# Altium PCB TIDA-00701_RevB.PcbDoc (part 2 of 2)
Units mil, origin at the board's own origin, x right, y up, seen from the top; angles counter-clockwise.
Board outline 4724.41 x 3228.35 mil, 2 copper layers (Top Layer, Bottom Layer), stack 62 mil thick; 170 components, 75 nets, 385 pads, 92 vias.
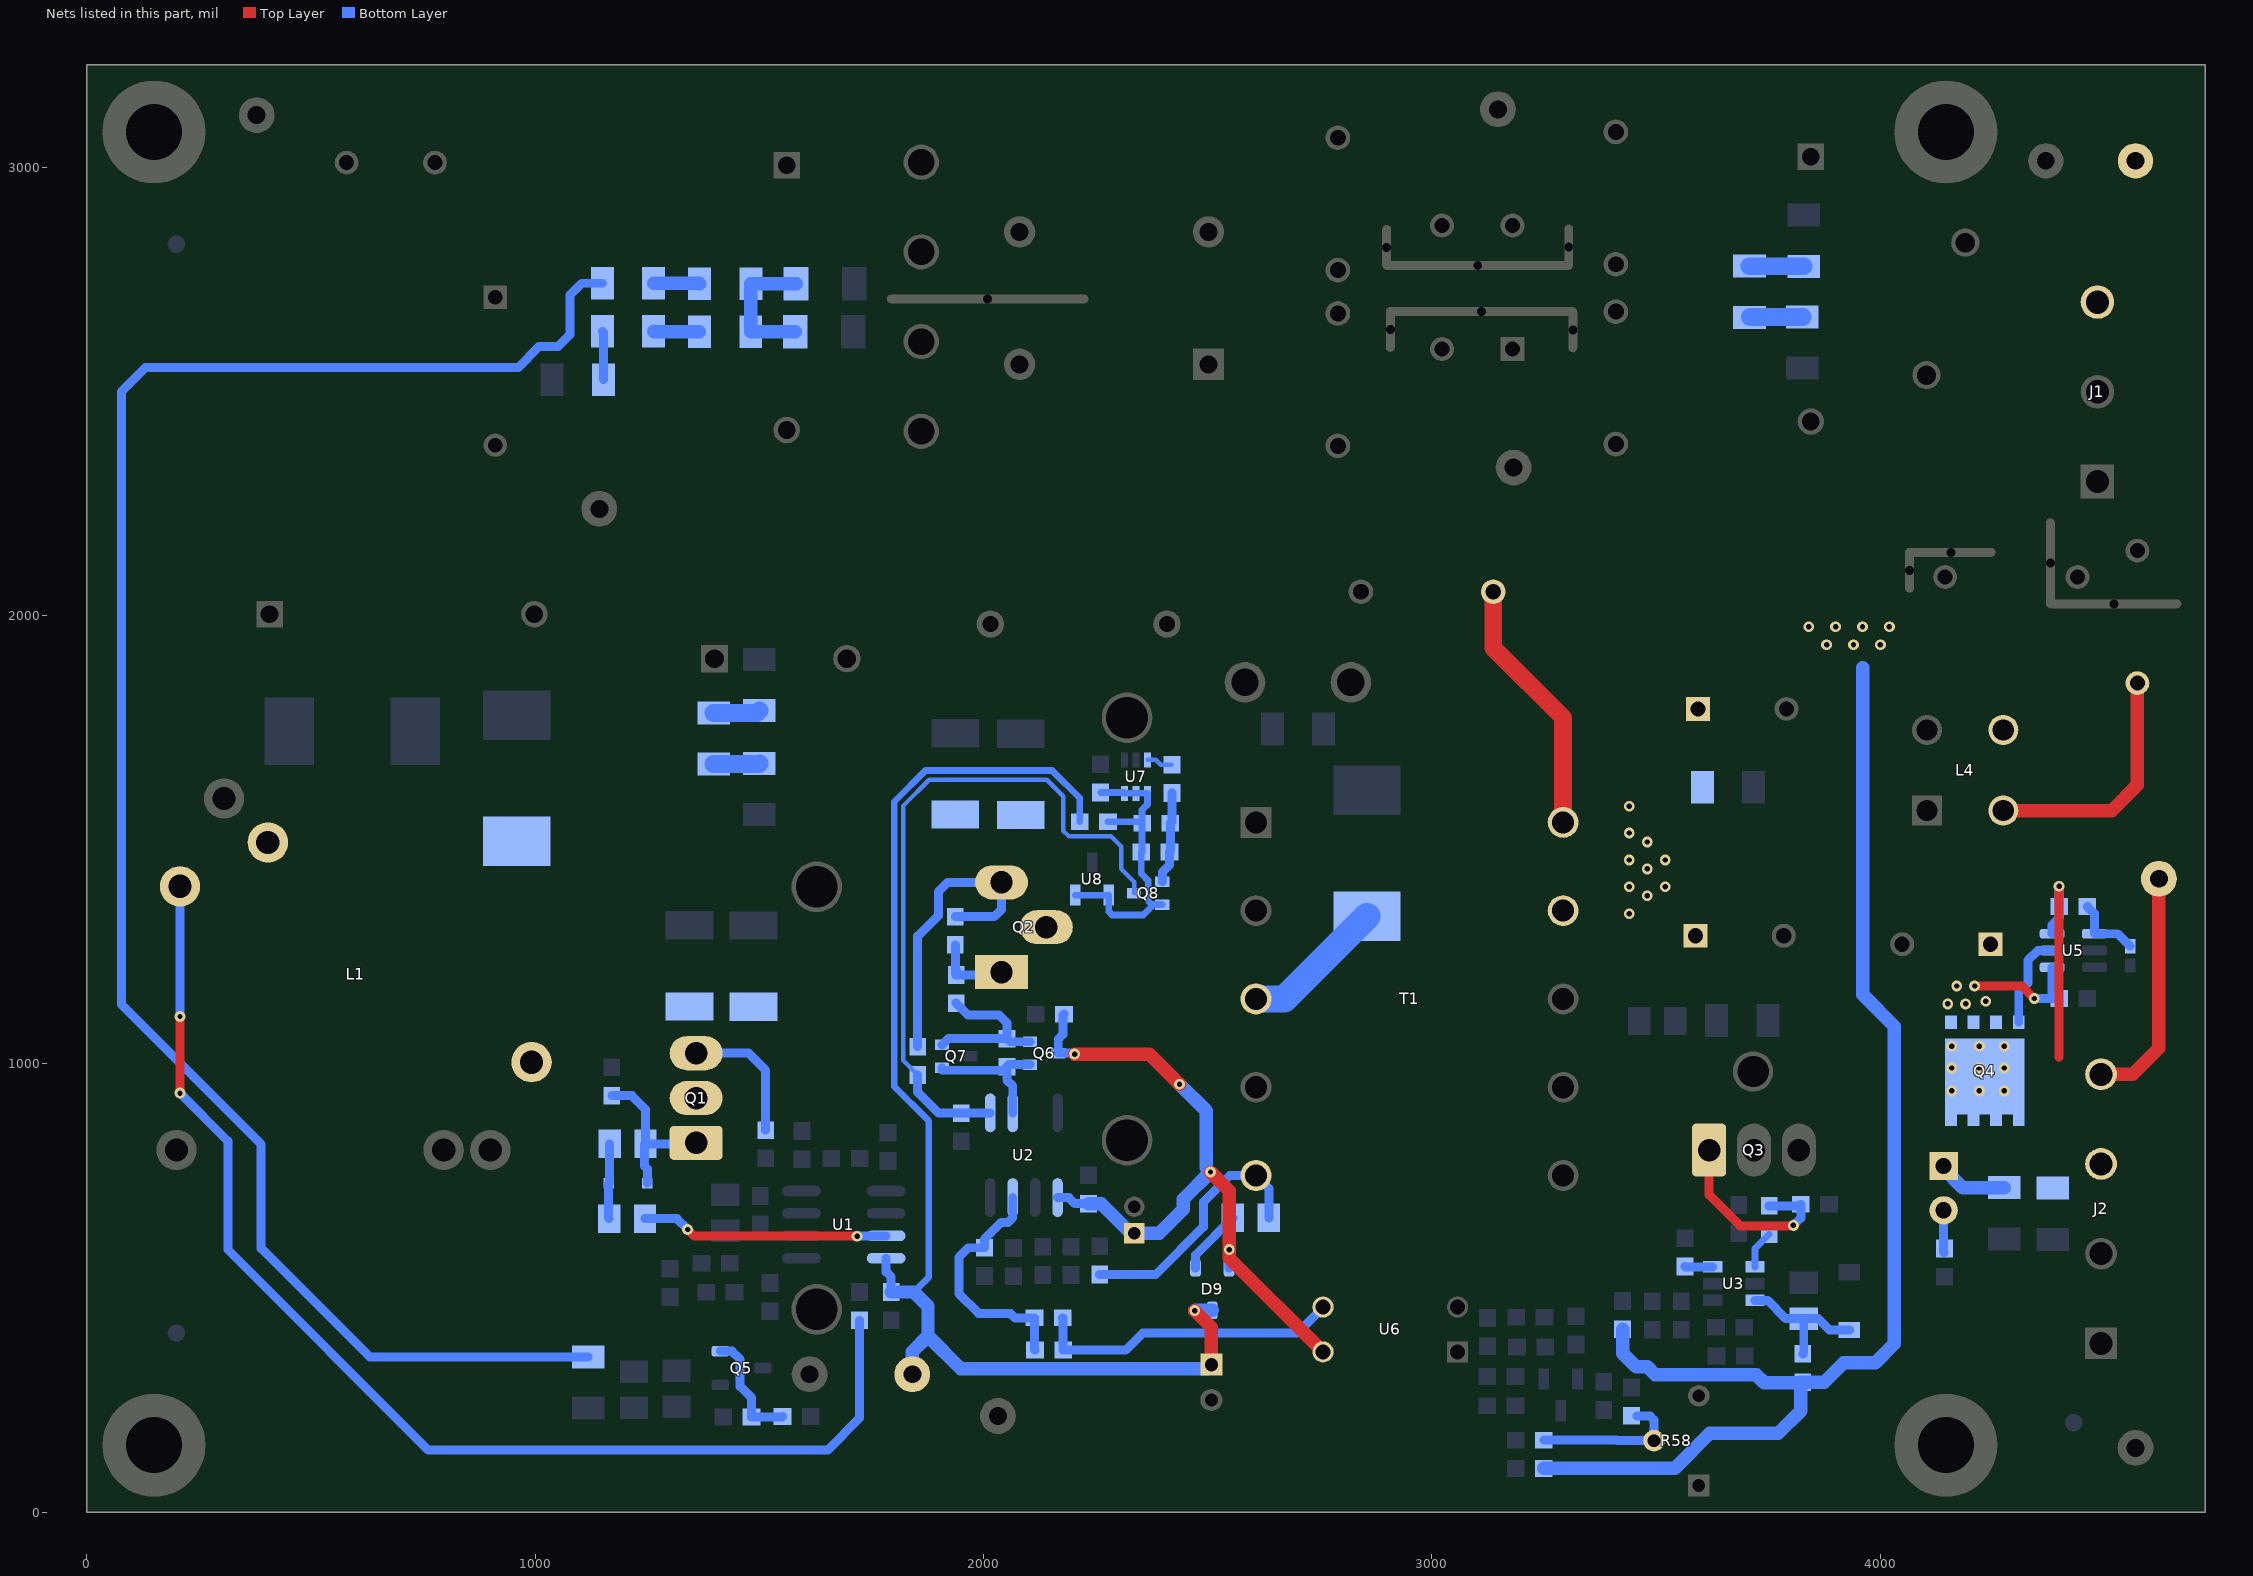
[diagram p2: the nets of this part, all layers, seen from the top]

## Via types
v1: diameter 24, hole 12, Top Layer to Bottom Layer, 92 vias

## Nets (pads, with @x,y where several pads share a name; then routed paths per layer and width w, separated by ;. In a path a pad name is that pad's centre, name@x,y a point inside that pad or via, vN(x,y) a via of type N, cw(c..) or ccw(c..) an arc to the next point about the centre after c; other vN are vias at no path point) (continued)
NetC29_1: C29.1 C30.1 C35.2 L4.4 R37.1 R42.1 R46.1 R53.2 T1.9 T1.10 | length 3528.3
  Top Layer w40: C35.2@3136.64,2053 3136.64,1928 3292.52,1772.12 T1.10@3292.52,1538.7
  Bottom Layer w30: R46.1@3249.5,98 3541.43,98 3619.59,176.16 3772,176.16 3822,226.16 R37.1@3822,290.5 ; R42.1@3425,408.5 3425,355 3455,325 3480.41,325 3498.11,307.3 3722.7,307.3 3740.5,289.5 3821,289.5 R37.1@3822,290.5 ; 3961,1884 3961,1154 4031,1084 4031,376 3989,334 3918,334 3874.5,290.5 R37.1@3827,290.5 R37.1@3822,290.5
  other v1: 3440,1335 3480,1375 3440,1395 3520,1395 3480,1435 3440,1455 3520,1455 3480,1495 3440,1515 3440,1575 3880,1935 3940,1935 4000,1935 3840,1975 3900,1975 3960,1975 4020,1975
NetC31_1: C31.1 C34.1 C39.1 L4.2 Q4.1 Q4.2 Q4.3 U5.4 | length 814.1
  Top Layer w20: v1(4210,1174) 4315,1174 v1(4343,1146)
  Top Layer w30: L4.2@4274.04,1565.04 4516.04,1565.04 4573,1622 C39.1@4573,1849.36
  Bottom Layer w20: v1(4343,1146) 4390,1146 4382.76,1153.24 U5.4@4382.76,1215.6
  other v1: 4150,1134 4190,1134 4235,1140 4170,1174
NetC32_1: C32.1 C33.1 D6.1 J2.3 J2.4 Q4.5 Q4.6 Q4.7 Q4.8 Q4.9 R52.1 TP8.1 U5.6 | length 1183.8
  Top Layer w20: 4398,1015 4398,1396 v1(4398.5,1396.5)
  Top Layer w30: J2.4@4492,977 4563,977 4621,1035 TP8.1@4621,1413
  Bottom Layer w20: U5.6@4382.76,1290.4 4382.76,1310.49 4398.5,1326.24 R52.1@4398.5,1351 v1(4398.5,1396.5)
  Bottom Layer w30: D6.1@4141,772.21 4141,766.21 4183.13,724.09 C32.1@4276,724.09
  other v1: 4158.98,940 4220.8,940 4276.11,940 4158.98,990.97 4220.8,990.97 4276.11,990.97 4158.98,1039.59 4220.8,1039.59 4276.11,1039.59
NetC36_1: C36.1 Q8.3 R29.1 U2.5 | length 1565.6
  Bottom Layer w10: R29.1@1853,975.5 1821.3,1007.2 1821.3,1576.3 1879,1634 2141,1634 2178,1597 2178,1519.73 2189.43,1508.3 2283.7,1508.3 2307,1485 2307,1435 2335.5,1406.5 Q8.3@2335.5,1381
  Bottom Layer w20: R29.1@1853,975.5 1853,937 1899.5,890.5 C36.1@1950,890.5 U2.5@2014.57,890.5
NetC37_2: C37.2 D11.1 R37.2 U3.6 | length 310.5
  Bottom Layer w20: U3.6@3720.24,472.6 3748.4,472.6 3789,432 C37.2@3822,432 ; R37.2@3827,353.5 3829,355.5 C37.2@3829,432 3861,432 3886,407 3930.53,407 D11.1@3931,406.53
NetC38_1: C38.1 R13.2 R34.2 U2.3 | length 556.9
  Bottom Layer w20: U2.3@2065.07,702.02 2065.07,657.07 2054.71,646.71 2039.56,646.71 2002,609.15 R34.2@2002,590.15 1966.15,590.15 1945,569 1945,488 1989,444 2060,444 2069.97,434.03 C38.1@2113.5,434.03 2113.5,363.03 R13.2@2114.5,362.03
NetC38_2: C38.2 R13.1 U6.3 | length 691.7
  Bottom Layer w20: C38.2@2176.5,434.03 2177.5,433.03 R13.1@2177.5,362.03 2317.03,362.03 2355,400 2699,400 U6.3@2757,458
NetC42_1: C42.1 Q8.1 R25.2 R33.1 | length 206.5
  Bottom Layer w20: Q8.1@2398.5,1406.59 2398.5,1427.5 2414.5,1443.5 R33.1@2414.5,1473 2416.5,1475 C42.1@2416.5,1537 2420,1540.5 R25.2@2420,1604.15
NetC42_2: C42.2 C43.1 Q8.2 R33.2 R35.2 U7.4 U7.5 U7.6 U8.1 U8.2 | length 693.8
  Bottom Layer w15: U8.2@2204.6,1376.57 U8.1@2279.4,1376.57 2279.4,1339.6 2286.56,1332.44 2356.06,1332.44 2377.31,1353.69 ; C43.1@2261,1605.5 2312.5,1605.5 U7.6@2314.41,1603.6 U7.5@2340,1603.6 U7.4@2365.59,1603.6 2365.59,1578.86 2353.5,1566.77 C42.2@2353.5,1537 ; R35.2@2277.5,1540 2350.5,1540 C42.2@2353.5,1537 ; R33.2@2351.5,1473 2351.5,1424.5 2367,1409 2367,1364 2377.31,1353.69 ; R33.2@2353.5,1470.83 C42.2@2353.5,1537 ; Q8.2@2398.5,1355.41 2379.03,1355.41 2377.31,1353.69
NetD1_2: D1.2 L1.2 L1.4 Q1.2
NetD3_1: D3.1 R14.1 R15.2 | length 168.5
  Bottom Layer w20: R15.2@1165,655 1163.69,656.31 D3.1@1163.69,734 1166,736.31 R14.1@1166,822
NetD3_2: D3.2 Q1.1 R14.2 R16.1 | length 369.9
  Bottom Layer w20: R16.1@1171,929.5 1215.5,929.5 1246,899 R14.2@1246,822 ; D3.2@1250.31,734 1250.31,765.69 1244,772 1244,820 R14.2@1246,822 ; Q1.1@1359,824 1357,822 R14.2@1246,822
NetD4_1: D4.1 D5.1 R3.1 R17.2 | length 306.5
  Bottom Layer w30: R3.1@1480.79,2633.06 R3.1@1480.79,2633.06 R17.2@1480.85,2740.1 ; R17.2@1480.89,2740.06 D4.1@1581.75,2740.06 ; R3.1@1481.2,2632.65 D5.1@1579.75,2632.65
NetD6_2: D6.2 R55.2 | length 94.2
  Bottom Layer w20: D6.2@4141,673.79 4141,581 R55.2@4142,580
NetD8_2: D8.2 Q2.2 T1.3 | length 323.9
  Bottom Layer w60: T1.3@2607.48,1145 2670.49,1145 D8.2@2855,1329.51
NetD9_1: D9.1 R30.1 | length 146.3
  Bottom Layer w20: D9.1@2472.6,545.24 2472.6,573.6 R30.1@2556,657
NetD12_1: D12.1 R52.2 U5.1 | length 158.4
  Bottom Layer w20: R52.2@4461.5,1351 4477.24,1335.25 U5.1@4477.24,1290.4 4529.25,1290.4 D12.1@4557,1262.65
NetF1_2: F1.2 J1.3 XF1.2
NetL1_8: L1.8 R12.2 | length 2695.4
  Top Layer w20: v1(208,935) v1(208,1106)
  Bottom Layer w20: v1(208,935) 315,828 315,586 762,139 1652,139 1723,210 R12.2@1723,428.5 ; v1(208,1106) L1.8@208,1396
NetQ1_3: Q1.3 R1.2 R2.2 R11.2 | length 304.2
  Bottom Layer w20: Q1.3@1359,1024 1476,1024 1514,986 R11.2@1514,852.5
NetQ2_1: Q2.1 R28.2 R47.2 | length 171.7
  Bottom Layer w20: R28.2@1937,1202.5 R47.2@1937,1265.5 ; R28.2@1938,1201.5 R28.2@1941.5,1205 ; R28.2@1939,1198.5 2033.5,1198.5 Q2.1@2040,1205
NetQ2_3: Q2.3 R26.2 R27.2 R29.2 R47.1 | length 684.1
  Bottom Layer w20: R29.2@1853,1038.5 1853,1285 1899,1331 1899,1384 1920,1405 Q2.3@2040,1405 2040,1345 2023.5,1328.5 R47.1@1937,1328.5
NetQ3_1: Q3.1 R43.1 R44.2 | length 442.4
  Top Layer w20: Q3.1@3618,808 3618,708 3687,639 v1@3806,639
  Bottom Layer w20: R44.2@3752,683.5 3819,683.5 R43.1@3822.5,687 3822.5,656.5 v1(3806,640)
NetQ4_4: Q4.4 U5.5 | length 209.1
  Bottom Layer w20: Q4.4@4308.49,1093.3 4308.49,1159.49 4329,1180 4329,1231 4351,1253 U5.5@4382.76,1253
NetQ5_2: Q5.2 R21.1 R60.2 | length 259.9
  Bottom Layer w20: Q5.2@1412.76,359.4 1438.6,359.4 1457,341 1457,281 1482.5,255.5 R21.1@1482.5,213 1550.5,213 R60.2@1551.5,214
NetQ6_1: Q6.1 Q7.1 R36.1 U2.6 | length 314.5
  Bottom Layer w20: Q7.1@1907.5,991.41 1907.5,986 2044.5,986 R36.1@2052,993.5 ; U2.6@2065.07,891 2065.07,950.93 2052,964 R36.1@2052,993.5 ; Q6.1@2103.5,998.41 2056.91,998.41 R36.1@2052,993.5
NetQ6_2: Q6.2 Q7.2 R28.1 R36.2 | length 370.9
  Bottom Layer w20: Q7.2@1907.5,1042.59 1921.41,1056.5 R36.2@2052,1056.5 ; R28.1@1939,1135.5 1965.22,1109.29 2034.29,1109.29 2052,1091.57 R36.2@2052,1056.5 ; Q6.2@2103.5,1049.59 2058.91,1049.59 R36.2@2052,1056.5
NetR3_2: R3.2 R4.1 | length 101.9
  Bottom Layer w30: R4.1@1264.09,2634 1265.03,2633.06 R3.2@1365.62,2633.06
NetR4_2: R4.2 R59.1 | length 108.9
  Bottom Layer w20: R4.2@1149.91,2634 1152.09,2631.83 R59.1@1152.09,2526
NetR6_2: R6.2 R7.2 | length 104
  Bottom Layer w40: R7.2@1398,1783.09 1495.17,1783.09 R6.2@1500,1787.91
NetR7_1: R7.1 R8.2 | length 102.5
  Bottom Layer w40: R7.1@1398,1668.91 1498.83,1668.91 R8.2@1500,1670.09
NetR15_1: R15.1 U1.7 | length 554.2
  Top Layer w20: v1(1340,631) 1355,616 v1(1718,616)
  Bottom Layer w20: R15.1@1245,655 1316,655 v1(1340,631) ; v1(1718,616) 1719,616 1719.72,616.72 U1.7@1782.71,616.72
NetR17_1: R17.1 R18.1 | length 101.9
  Bottom Layer w30: R18.1@1264.14,2741.04 R17.1@1364.73,2741.04 ; R17.1@1365.73,2741.04 R17.1@1366.67,2740.1
NetR18_2: R18.2 R19.2 | length 4093.6
  Bottom Layer w20: R19.2@1118.22,346.81 631.19,346.81 389,589 389,821 77,1133 77,2499 131,2553 961.92,2553 1008.46,2599.54 1050.54,2599.54 1077.92,2626.92 1077.92,2714.92 1104.04,2741.04 R18.2@1149.97,2741.04
NetR22_2: R22.2 R23.1 | length 121.1
  Bottom Layer w30: R23.1@3708,2779.09 R23.1@3708.17,2778.91
  Bottom Layer w40: R23.1@3708.17,2778.91 R22.2@3829,2778.91
NetR23_2: R23.2 R24.1 | length 118.5
  Bottom Layer w30: R23.2@3708,2664.91 R23.2@3709.17,2666.09
  Bottom Layer w40: R23.2@3709.17,2666.09 R24.1@3826,2666.09
NetR25_1: R25.1 U7.3 | length 59.1
  Bottom Layer w10: U7.3@2365.59,1678.4 2383.98,1678.4 2395.24,1667.14 R25.1@2420,1667.14
NetR30_2: R30.2 R31.2 T1.5 | length 578.5
  Bottom Layer w20: R31.2@2259,530.5 2383.91,530.5 2490,636.6 2490,692 2549.3,751.3 T1.5@2607.48,751.3 2636,722.78 R30.2@2636,657
NetR40_1: R40.1 U3.3 | length 62.2
  Bottom Layer w20: R40.1@3564,548.5 3565.1,547.4 U3.3@3625.76,547.4
NetR44_1: R44.1 U3.4 | length 86.3
  Bottom Layer w15: U3.4@3720.24,547.4 3720.24,588.75 R44.1@3752,620.5
NetR56_1: R56.1 R57.2 R58.2 | length 333.5
  Bottom Layer w20: R56.1@3249.5,161 3411,161 3412,160 R58.2@3495.06,160 3495.06,205.94 3486.5,214.5 R57.2@3457,214.5
VCC: C9.1 C19.1 D9.3 R35.1 TP3.1 U1.8 | length 2842.9
  Top Layer w30: v1(2471,450) 2508,413 C19.1@2508,329.37
  Bottom Layer w15: 1844.5,491.5 1878,524.99 1878,872.4 1800.8,949.6 1800.8,1584.79 1870.51,1654.5 2153.03,1654.5 2214.5,1593.02 R35.1@2214.5,1540
  Bottom Layer w20: U1.8@1782.71,566.72 1782.71,536.29 1794,525 C9.1@1794,491.5
  Bottom Layer w30: C9.1@1794,491.5 1844.5,491.5 1876,460 1876,393.33 ; TP3.1@1841,308 1841,358.33 1876,393.33 ; v1(2471,450) 2471.76,450.76 D9.3@2510,450.76 ; C19.1@2508,329.37 2498.96,320.33 1949,320.33 1876,393.33
VDD: C20.1 C21.1 C41.1 D9.2 Q6.3 U2.1 U6.4 | length 1592.6
  Top Layer w30: v1(2203,1022) 2370,1022 v1(2437,955) ; v1(2506,759) 2548,717 v1(2548,586) 2548,567 U6.4@2757,358
  Bottom Layer w20: U2.1@2165.07,702.02 2189.98,702.02 2203.5,688.5 C21.1@2234,688.5 ; C41.1@2179.5,1111 2177,1108.5 2177,1066 2166.5,1055.5 Q6.3@2166.5,1024 2201,1024 v1(2203,1022) ; C20.1@2328.53,622.47 C20.1@2336,622.47 ; D9.2@2547.4,545.24 2547.4,583.4 2548,584 v1(2548,586)
  Bottom Layer w30: C21.1@2234,688.5 2262.5,688.5 C20.1@2328.53,622.47 ; C20.1@2336,622.47 2391.47,622.47 2445,676 2445,698 v1(2506,759) ; v1(2437,955) 2497,895 2497,768
pads on no net: FID1.1 FID2.1 FID3.1 H1.1 H2.1 H3.1 H4.1 R58.1 T1.2 T1.8

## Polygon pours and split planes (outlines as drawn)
NetC29_1 on Bottom Layer "Top Layer-No Net" (solid, remove dead copper, pour order 52): 3246,1710 3246,1519 3246,1246 3264,1228 3287,1228 3618,1228 3632,1242 3632,1310 3632,1825 3668,1861 3692,1861 4182,1861 4237,1806 4238,1805 4238,1753 4238,1721 4250,1709 4286,1709 4337,1709 4346,1718 4347,1719 4347,1754 4347,1959 4301,2005 3462,2005 3429,1972 3429,1925 3429,1742 3412,1725 3261,1725
NetC31_1 on Bottom Layer "Top Layer-No Net" (solid, remove dead copper, pour order 48): 4236,1589 4218,1571 4186,1539 4186,1302.2 4173,1289.2 4173,1261 4178,1256 4201,1233 4231,1233 4285,1233 4316,1264 4316,1362 4370,1416 4370,1564 4370,1580 4355,1595 4350,1600 4268,1600 4247,1600
NetC3_1 on Bottom Layer "M9 Title Sheet-No Net" (solid, pour order 79): 4342,3056 4331,3045 4331,3027 4331,2985 4322,2976 4209,2863 4191,2863 4176,2863 4164,2875 4124,2915 4091,2915 4017,2915 3871,3061 3815,3061 3771,3061 3767,3065 3712,3120 3413,3120 3315,3120 3157,2962 3152,2957 3152,2888 3152,2852 3161,2843 3163,2841 3199,2841 3226,2841 3230,2845 3241,2856 3241,2884 3241,2893 3291,2943 3338,2990 3668,2990 3794,2864 3885,2864 3966,2783 4140,2783 4156,2799 4158,2801 4169,2801 4221,2801 4232,2790 4237,2785 4301,2785 4411,2895 4411,3043 4398,3056
NetC18_2 on Bottom Layer "M9 Title Sheet-No Net" (solid, remove dead copper, pour order 78): 2731,1886 2731,1642 2731,1560 2743,1548 2748,1543 2803,1543 2928,1543 2933,1548 2934,1549 2934,1586 2934,1870 2908,1896 2905,1899 2844,1899 2744,1899
NetC8_1 on Bottom Layer "M9 Title Sheet-No Net" (solid, remove dead copper, pour order 77): 2454,2590 2454,2523 2472,2505 2652,2325 2788,2325 2906,2325 2952,2371 3050,2469 3050,2518 3050,2612 3041,2621 3040,2622 3020,2622 3006,2622 2997,2613 2992,2608 2992,2592 2992,2588 2986,2582 2854,2450 2820,2450 2701,2450 2663,2488 2553,2598 2533,2598 2463,2598 2462,2597 2454,2589
NetC7_1 on Bottom Layer "M9 Title Sheet-No Net" (solid, remove dead copper, pour order 76): 2454,2825.91 2465.92,2814 2568,2814 2586,2832 2586,2879 2701,2994 2855,2994 3008,2841 3042,2841 3051,2850 3051,2894 3051,2973 2905,3119 2775,3119 2653,3119 2554,3020 2454,2920
NetD1_2 on Bottom Layer "M9 Title Sheet-No Net" (solid, remove dead copper, pour order 75): 372,1543 817,1543 834.25,1560.25 1027.76,1560.25 1040.03,1547.97 1040,1438.75 1040,1010 1040,973 1032,965 1017,950 963,950 947,966 947,1010 947,1413 921,1439 372,1439 362,1449 359,1452 359,1484 359,1530
NetC32_1 on Bottom Layer "M9 Title Sheet-No Net" (solid, remove dead copper, pour order 74): 4144,1058 4319,1058 4328,1058 4340,1046 4349,1037 4398,1037 4518,1037 4532,1023 4539,1016 4539,901 4539,712 4526,699 4262,699 4237,699 4220,716 4220,756 4220,817 4205,832 4202,835 4152,835 4146,835 4137,844 4134.57,846.43 4134.57,892 4134.57,1053.57 4139,1058
NetC2_1 on Bottom Layer "M9 Title Sheet-No Net" (solid, remove dead copper, pour order 71): 2379,1961 2518,1822 2518,1808 2518,1522 2531,1509 2538,1502 2569,1502 2643,1502 2672,1531 2672,1739 2672,2107 2661,2118 2659,2120 2464,2120 2395,2120 2382,2107 2379,2104 2379,2032 2379,1961
GND on Bottom Layer "M9 Title Sheet-No Net" (solid, remove dead copper, pour order 70): 883,2397 889,2403 893,2407 924,2407 1221,2407 1359,2269 1370,2258 1435,2258 1920,2258 2053,2125 2082,2096 2082,1896 2082,1893.89 2113,1862.89 2113.89,1862 2227,1862 2306,1862 2376,1792 2384,1784 2384,1752 2384,1742 2357.13,1715.13 2353,1711 2353,1664 2353,1662.28 2337.72,1647 2228,1647 2207,1668 2179,1696 2163,1696 1805,1696 1796,1705 1796,1780 1789,1787 1778,1787 1772,1781 1772,1757 1772,1400 1704,1332 1633,1261 1415,1261 1269,1261 1247,1283 1247,1465 1271,1489 1272,1488 1431,1488 1632,1488 1664,1520 1664,1979 1664,2058 1625,2097 1315,2097 1123,2097 1088,2062 1088,2002 1088,1988 1071,1971 900,1971 883,1988 883,2050 883,2344
NetBR1_1 on Bottom Layer "M9 Title Sheet-No Net" (solid, remove dead copper, pour order 66): 1838,2971 1897,2971 1899,2971 1911,2983 1914,2986 1914,3056 1914,3071 1903,3082 1895,3090 1834,3090 1692,3090 1660,3090 1639,3090 1590,3041 1584,3035 1570,3035 1525,3035 1492,3068 1476,3084 1441,3084 770,3084 757,3071 751,3065 751,3024 751,2982 751,2961 751,2960 761,2950 769,2942 913,2942 1479,2942 1496,2959 1511,2974 1536,2974 1594,2974 1631,2937 1644,2924 1701,2924 1756,2924 1793,2961 1803,2971
NetBR1_2 on Bottom Layer "Bottom Layer-No Net" (solid, remove dead copper, pour order 54): 2105,2771 2123,2789 2123,2790 2123,2813 2123,2889 2123,2908 2117,2914 2116,2915 2072,2915 1989,2915 1926,2852 1925,2851 1904,2851 1829,2851 1821,2843 1821,2789 1821,2778 1827,2772 1828,2771 1852,2771 2105,2771
NetBR1_3 on Bottom Layer "Bottom Layer-No Net" (solid, remove dead copper, pour order 55): 2110.63,2652.64 2128.63,2634.64 2128.63,2633.64 2128.63,2610.64 2128.63,2534.64 2128.63,2515.64 2122.63,2509.64 2121.63,2508.64 2077.63,2508.64 1994.63,2508.64 1931.63,2571.64 1930.63,2572.64 1909.63,2572.64 1834.63,2572.64 1826.63,2580.64 1826.63,2634.64 1826.63,2645.64 1832.63,2651.64 1833.63,2652.64 1857.63,2652.64 2110.63,2652.64
GNDE on Bottom Layer "Bottom Layer-No Net" (solid, remove dead copper, pour order 46): 4441,2334 4441,2173 4420,2152 4410,2142 4410,2088 4410,2071 4415,2066 4423,2058 4451,2058 4481,2058 4482,2058 4489,2065 4493,2069 4493,2098 4493,2106 4501,2114 4502,2115 4552,2115 4602,2115 4605,2118 4606,2119 4606,2148 4606,2314 4606,2326 4595,2337 4593,2339 4506,2339 4445,2339 4441,2335
NetF1_2 on Bottom Layer "Bottom Layer-No Net" (solid, remove dead copper, pour order 41): 4531,3059 4528,3056 4528,2974 4528,2790 4513,2775 4497,2759 4476,2759 4448,2759 4445,2756 4438,2749 4438,2727 4438,2674 4443,2669 4452,2660 4485,2660 4641,2660 4654,2673 4659,2678 4659,2799 4659,3057 4651,3065 4537,3065
GND on Bottom Layer "Top Layer-NetL_1" (solid, remove dead copper, pour order 47): 1922,379 1923,378 1923,124 1923,81 1948,56 1951,53 2068,53 2617,53 2663,99 2668,104 2668,133 2668,966 2631,1003 2433,1003 2191.08,761.08 2151,761.08 2115.92,761.08 2044,833 2043,834 2043,989 2043,1042 2019,1066 2017,1068 1864,1068 1836,1068 1806,1038 1804,1036 1804,932 1852,884 1921,815 1921,754
GND on Bottom Layer "Top Layer-NetL_1" (solid, remove dead copper, pour order 43): 1507,918 1763,918 1800,881 1885,796 1885,705 1885,91 1865,71 1857,63 1645,63 403,63 383,83 327.65,138.35 327.65,556.1 327.65,566.28 359.63,598.27 412.37,651 949,651 1320,651 1356,687 1411,742 1464,742 1471,742 1504,775 1508,779 1508,900 1508,910 1516,918
GND-3 on Bottom Layer "Top Layer-NetL_1" (solid, remove dead copper, pour order 44): 4469,1265 4512,1265 4512,1264 4520,1256 4520,1248 4526,1242 4532,1236 4549,1236 4585,1236 4589,1232 4589,1221 4589,1180 4586,1177 4531,1177 4521,1167 4521,1119 4514,1112 4447,1112 4442,1112 4438,1116 4438,1126 4438,1254 4449,1265
NetQ1_3 on Bottom Layer "Bottom Layer-No Net 6" (solid, remove dead copper, pour order 56): 1274,1164 1274,1003 1292,985 1415,985 1430,1000 1430,1054 1449,1073 1541.56,1073 1559,1090.44 1559,1162.97 1551.96,1170.01 1280.01,1170.01
NetQ2_3 on Bottom Layer "Bottom Layer-No Net 3" (solid, remove dead copper, pour order 49): 1878,1587 1889,1598 2137.96,1598 2147.96,1588 2147.96,1420.96 2095,1368 1886,1368 1878,1376
NetC31_1 on Bottom Layer "Bottom Layer-No Net 8" (solid, remove dead copper, pour order 58): 4186,1302.2 4283.8,1302.2 4296,1290 4296,1193 4279,1176 4279,1075.2 4276,1072.2 4135,1072.2 4129,1078.2 4129,1190.2 4173,1234.2 4173,1289.2
GND-3 on Bottom Layer "Bottom Layer-No Net 11" (solid, remove dead copper, pour order 57): 4645,641 4654,632 4654,286.67 4644.33,277 4641.33,280 4281,280 4228.36,332.64 4228.36,630.36 4239,641
NetC28_2 on Bottom Layer "Top Layer-No Net 11" (solid, remove dead copper, pour order 62): 3254,978 3255,977 3255,721 3271,705 3524,705 3541,722 3541,853 3576,888 3652,888 3677,863 3677,747 3694,730 3745,730 3759,744 3759,916 3746,929 3683,929 3613,999 3275,999
GND-2 on Bottom Layer "Bottom Layer-No Net 4" (solid, remove dead copper, pour order 63): 3692,1792 3692,1012.25 3779,925.25 3779,570 3766,557 3766,532 3760,526 3699,526 3692,519 3692,497 3697,492 3760,492 3775,477 3966,477 3986,497 3986,1057 3885,1158 3885,1796 3863,1818 3862,1817 3717,1817
GND-3 on Top Layer "Top Layer-No Net" (solid, remove dead copper, pour order 45): 4070,1598 4138,1598 4144,1592 4145,1591 4145,1555 4145,1528 4137,1520 4135,1518 4127.4,1518 4114,1504.6 4113,1503.6 4113,1276 4087,1250 4087,1122 4087,619 4096,610 4122,610 4637,610 4649,598 4655,592 4655,583.42 4655,287.67 4645.33,278 4644.33,277 4634,277 4117,277 4106.33,287.67 3932,462 3932,499 3932,1505 3977,1550 4025,1598 4069,1598
GND-2 on Top Layer "Top Layer-No Net" (solid, pour order 42): 3151,524 3151.2,523.8 3151.2,436 3151.2,65.8 3172,45 3224,45 3873,45 3888,60 3888,171.5 3888,1577 3904,1593 3985,1674 4076.05,1674 4103,1674 4123,1674 4127,1674 4132,1674 4137,1679 4143,1685 4143,1693 4143,1807 4137,1813 4132,1818 4048,1818 3718,1818 3692,1792 3692,1685 3692,1012 3781,923 3781,831 3781,709 3753,681 3567,681 3545,659 3502,616 3502,598 3502,556 3479,533 3160,533
NetC3_2 on Top Layer "M9 Title Sheet-No Net" (solid, pour order 80): 3151,2621 3146,2616 3146,2515 3146,2502 3232,2416 3310,2338 3322,2326 3488,2326 3739,2326 3787,2374 3814,2401 3853,2401 3877,2401 3894,2384 3977,2384 4096,2503 4142,2503 4187,2458 4297,2458 4515,2458 4526,2469 4526,2523 4512,2537 4416.85,2537 4371.85,2582 4361,2582 4153,2582 4139,2568 4024,2568 3932,2476 3721,2476 3372,2476 3215,2633 3185,2633 3163,2633
NetC32_1 on Top Layer "M9 Title Sheet-No Net" (solid, remove dead copper, pour order 73): 4144,1058 4319,1058 4328,1058 4340,1046 4349,1037 4398,1037 4518,1037 4532,1023 4539,1016 4539,901 4539,712 4526,699 4262,699 4237,699 4220,716 4220,756 4220,817 4205,832 4202,835 4152,835 4146,835 4137,844 4134.57,846.43 4134.57,892 4134.57,1053.57 4139,1058
NetC2_1 on Top Layer "M9 Title Sheet-No Net" (solid, remove dead copper, pour order 72): 2379,2104 2379,1978 2379,1962 2428,1913 2542,1799 2612,1799 2650,1799 2664,1813 2672,1821 2672,1841 2672,2107 2659,2120 2395,2120 2393,2118
NetBR1_4 on Top Layer "M9 Title Sheet-No Net" (solid, remove dead copper, pour order 69): 904,2772 1181,2772 1212,2741 1511,2442 1518,2442 1582,2442 1609,2469 1621,2481 1759,2481 1771,2481 1799,2453 1891,2453 1905,2439 1906,2438 1906,2394 1906,2384 1892,2370 1891,2369 1818,2369 1606,2369 1594,2381 1593,2382 1572,2382 1531,2382 1512,2363 1376,2363 1318,2421 1105,2634 1030,2634 895,2634 880,2649 880,2753 880,2755.3 894.7,2770 897,2772
NetD1_2 on Top Layer "M9 Title Sheet-No Net" (solid, remove dead copper, pour order 68): 947,1033 947,973 962,958 965,955 1031,955 1156,955 1204,907 1227,884 1254,884 1405,884 1421,900 1421,943 1403,961 1402,962 1314,962 1249,962 1162,1049 963,1049
NetC1_1 on Top Layer "M9 Title Sheet-No Net" (solid, remove dead copper, pour order 67): 254,1898 254,1608 254,1572 274,1552 278,1548 332,1548 365,1581 365,1667 390,1692 454,1692 467,1705 467,1946 438,1975 438,2035 438,2036 485,2083 489,2087 489,2116 489,2903 526,2940 527,2939 593,2939 608,2954 608,3029 594,3043 532,3043 359,3043 350,3034 347,3031 347,2955 347,2065 377,2035 378,2034 378,2004 378,1977 344,1943 299,1943 254,1898
NetBR1_3 on Top Layer "Bottom Layer-No Net" (solid, remove dead copper, pour order 51): 2110.63,2652.64 2128.63,2634.64 2128.63,2633.64 2128.63,2610.64 2128.63,2534.64 2128.63,2515.64 2122.63,2509.64 2121.63,2508.64 2077.63,2508.64 1994.63,2508.64 1931.63,2571.64 1930.63,2572.64 1909.63,2572.64 1834.63,2572.64 1826.63,2580.64 1826.63,2634.64 1826.63,2645.64 1832.63,2651.64 1833.63,2652.64 1857.63,2652.64 2110.63,2652.64
NetBR1_2 on Top Layer "Bottom Layer-No Net" (solid, remove dead copper, pour order 53): 2105,2771 2123,2789 2123,2790 2123,2813 2123,2889 2123,2908 2117,2914 2116,2915 2072,2915 1989,2915 1926,2852 1925,2851 1904,2851 1829,2851 1821,2843 1821,2789 1821,2778 1827,2772 1828,2771 1852,2771 2105,2771
GND on Top Layer "Top Layer-No Net 8" (solid, remove dead copper, pour order 59): 2321,1850 2391,1780 2391,1492 2369,1470 1989,1470 1949,1430 1949,1152.27 1966,1135.27 2121.73,1135.27 2137,1120 2137,921 2155,903 2137,867 2117,847 1871.84,847 1797.13,921 1784,934 1784,1797 1837,1850
GND on Top Layer "Top Layer-No Net 9" (solid, remove dead copper, pour order 60): 1730,1489 1763,1456 1763,927 1787,903 1769,885 1508,885 1508,1056 1478,1086 1267,1086 1247,1106 1247,1465 1271,1489
NetD8_2 on Top Layer "Bottom Layer-No Net 5" (solid, remove dead copper, pour order 50): 2405,1344 2554,1195 2637,1195 2646,1186 2646,1116 2630,1100 2456,1100 2290,1266 2096,1266 2080,1282 2080,1324 2100,1344
NetC28_2 on Top Layer "Top Layer-No Net 11" (solid, remove dead copper, pour order 61): 3254,978 3255,977 3255,721 3271,705 3524,705 3541,722 3541,853 3576,888 3652,888 3677,863 3677,747 3694,730 3745,730 3759,744 3759,916 3746,929 3683,929 3613,999 3275,999
GND on Top Layer "Bottom Layer-No Net" (solid, remove dead copper, pour order 64): 1512.32,904.32 2200.32,904.32 2299,1003 2397,1003 2631,1003 2667,967 2667,87 2667,86 2625,44 2624,45 2541,45 129,45 73,101 57,117 57,283.75 57,873 67,883 72,888 577,888 888,888 960,816 1053,723 1117,723 1447,723 1508,784 1508,900
NetC29_1 on Top Layer "Bottom Layer-No Net" (solid, remove dead copper, pour order 65): 3246,1710 3246,1318 3246,1249 3267,1228 3586,1228 3618,1228 3632,1242 3632,1310 3632,1825 3668,1861 3670,1863 3764,1863 4047,1863 4053,1869 4060,1876 4060,1992 4060,1999 4054,2005 4053,2006 4014,2006 3463,2006 3429,1972 3429,1861 3429,1742 3412,1725 3261,1725 3254,1718

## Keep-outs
Keep-Out Layer:
  lines w10: 25,25 25,3196 4681,3196 4681,25 25,25

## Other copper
Top Layer:
  pour cut-out: 1763,1310.85 1763,927 1893,797 1893,50 1914,50 1914,60.01 1914.42,60.42 1914,60.84 1914,809 1901,822 1784,939 1784,1312 1779,1317 1756.58,1317
  pour cut-out: 1914.42,69.58 1934.28,49.72 1915.96,49.72 1914.42,51.27
  pour cut-out: 1874.42,51.82 1894.28,71.68 1894.28,53.37 1892.73,51.82
  text ".Layer_Name" at 577,-858.49 h60
Bottom Layer:
  pour cut-out: 4275.2,1128.07 4279,1128.07 4279,1138 4275.2,1134.2
  text ".Layer_Name" at 577,-858.49 h60

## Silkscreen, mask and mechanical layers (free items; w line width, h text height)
Top Overlay:
  circle w10: c4506,2179 r8.25
  circle w6: c322.38,2013 r7.62
  circle w6: c3620,720 r9.22
  circle w6: c2139,1184 r10.3
  circle w6: c2600,2366 r6.32
  circle w6: c3844,3098 r7.07
  circle w6: c890,2802 r7.62
  circle w6: c1446,808 r7.62
  circle w6: c4080,817 r10.77
  lines w6: 3502,1498 3533,1498 ; 3516,1482 3516,1513 ; 100,1700 100,1700 ; 100,1700 100,800 200,700 1075,700 1100,700 ; 100,1700 1000,1700 1100,1600 1100,700 ; 1100,700 1100,700
  text ".PCB_Rev" at 875,324 h60
  text ".PRJ_Number" at 252,323 h60
  text "-" at 812,323 h60
  text ".Layer_Name" at 577,-858.49 h60
Bottom Overlay:
  circle w6: c2184,646 r6.71
  circle w6: c3227,331 r3.61
  circle w6: c3594,447 r5
  circle w6: c4112.28,1117 r7.28
  circle w6: c2284,1334 r4.12
  circle w6: c2298,1703 r3.16
  circle w6: c1526,567 r8.54
  lines w6: 1364,596 1364,642 ; 1473,753 1479,747 1479,742 ; 1548,413 1548,409 1557,400 ; 2157,474 2179,474 2184,469 2211,469 2249,431 2249,412 2257,420 2240,420 2248,412 ; 2376.69,1703 2376.69,1705.69 2388,1717 ; 3276.01,519 3273.01,516 3282,516 3279,519 3279,505 3287,497 3287,402 ; 3348,332 3353,332 3358,337 ; 3533,336 3533,365 ; 3674,735 3738,735 3751,722 ; 3731,394 3747,394 3774,367 3774,338 ; 3763,564 3770,564 ; 3860,565 3860,573
  text ".Layer_Name" at 577,-858.49 h60
Top Paste:
  text ".Layer_Name" at 577,-858.49 h60
Bottom Paste:
  text ".Layer_Name" at 577,-858.49 h60
Top Solder:
  text ".Layer_Name" at 577,-858.49 h60
  text ".Layer_Name" at 577,-858.49 h60
Bottom Solder:
  text ".Layer_Name" at 577,-858.49 h60
Drill Guide:
  text ".Layer_Name" at 577,-858.49 h60
M1 Board Outline:
  the board outline again, w10
M2 Board Dimensions:
  rectangle: 0,-285.5 125,-160.5
  rectangle: 125,-410.5 500,-285.5
  lines w7: 0,-285.5 1000,-285.5 ; 125,-410.5 125,-160.5 ; 250,-410.5 250,-160.5 ; 500,-410.5 500,-160.5 ; 750,-410.5 750,-160.5 ; 0,-410.5 1000,-410.5 1000,-160.5 0,-160.5 0,-410.5
M3 3D STEP Top:
  text ".Layer_Name" at 577,-858.49 h60
M4 3D STEP Bottom:
  text ".Layer_Name" at 577,-858.49 h60
M5 Assembly Top:
  circle w6: c910,2709 r13.78
  circle w6: c4469,2233 r11.18
  circle w6: c4139,763 r7.81
  circle w6: c4492,377 r18.03
  circle w6: c3618,808 r13.34
  circle w6: c3845,3020 r10.77
  circle w6: c3230.63,2505.36 r10.33
  circle w6: c2500,2555 r10.18
  circle w6: c407,2001 r11
  circle w6: c1555,2998 r13.78
  circle w6: c2056,1199 r10
  circle w6: c1359,824 r13.6
  circle w10: c4103.96,1565.04 r12.1
  lines w6: 3524,1517 3549,1517 ; 3536,1505 3536,1530
  lines w10: -292,-930.17 6308,-930.17 ; -292,-726.83 6310,-726.83 ; -292,-523.5 -292,-1133.5 3713,-1133.5 6310,-1133.5 6310,-523.5 -291.5,-523.5 -291.5,-1133.5 1284,-1133.5 ; 2173,-1133.5 2173,-523.5 ; 3440,-726.83 3440,-523.5 ; 4280,-726.83 4280,-523.5 ; 4902,-1140 4902,-937.17
  text "COMPONENTS MARKED 'DNP' SHOULD NOT BE POPULATED." at 1153.5,-318.5 h60
  text "ASSEMBLY VARIANT:" at 1153,-434 h60
  text ".VariantName" at 2189,-434 h60
  text "PCB VIEWED FROM TOP SIDE" at -228.5,-655.67 h60
  text "BOARD #:" at 2248,-655.67 h60
  text ".PRJ_Number" at 2793.5,-655.67 h60
  text "REV:" at 3638,-655.67 h60
  text ".PCB_Rev" at 3929.5,-655.67 h60
  text "SVN REV:" at 4476,-655.67 h60
  text ".VersionControl_RevNumber" at 4982,-655.67 h60
  text ".Layer_Name" at 588,-851 h60
  text "IGNORE ->" at -228.5,-858.49 h60
  text "PLOT NAME =" at -228.5,-1064.34 h60
  text ".plot_File_Name" at 577,-1064.34 h60
  text "GENERATED    :" at 2250,-1064.34 h60
  text ".Print_Date" at 3119.5,-1064.34 h60
  text ".Print_Time" at 3848.5,-1064.34 h60
  text "TEXAS INSTRUMENTS" at 5113,-1064.34 h60
M6 Assembly Bottom:
  circle w6: c1629,564 r8.06
  circle w6: c1450,282 r6.08
  circle w6: c2474,507 r6.08
  circle w6: c2160,743 r8.06
  circle w6: c1899,968 r6.08
  circle w6: c2101.08,972 r6.08
  circle w6: c2281,1401 r6.08
  circle w6: c2429,1411 r6.08
  circle w6: c3249,272 r6.08
  circle w6: c4477.24,1290.4 r8.28
  lines w6: 4493,1307 4510,1307 4510,1198 4349,1198 4349,1307 4503,1307
  lines w10: -292.5,-727.33 6309.5,-727.33 ; -290.5,-930.67 6309.5,-930.67 ; 1115.5,-1140.5 1115.5,-937.67 ; 1737.5,-727.33 1737.5,-524 ; 2577.5,-727.33 2577.5,-524 ; 3844.5,-1134 3844.5,-524 ; 4733.5,-1134 6309,-1134 6309,-524 -292.5,-524 -292.5,-1134 2304.5,-1134 6309.5,-1134 6309.5,-524
  text "COMPONENTS MARKED 'DNP' SHOULD NOT BE POPULATED." at 6102,-318 h60
  text ".VariantName" at 5058,-434 h60
  text "ASSEMBLY VARIANT:" at 6097,-434 h60
  text ".VersionControl_RevNumber" at 1035.5,-656.17 h60
  text "SVN REV:" at 1541.5,-656.17 h60
  text ".PCB_Rev" at 2088,-656.17 h60
  text "REV:" at 2379.5,-656.17 h60
  text ".PRJ_Number" at 3224,-656.17 h60
  text "BOARD #:" at 3769.5,-656.17 h60
  text "PCB VIEWED FROM BOTTOM SIDE" at 6246,-656.17 h60
  text "IGNORE ->" at 2547.85,-858.49 h60
  text ".Layer_Name" at 1893,-863 h60
  text "TEXAS INSTRUMENTS" at 904.5,-1064.84 h60
  text ".Print_Time" at 2169,-1064.84 h60
  text ".Print_Date" at 2898,-1064.84 h60
  text "GENERATED    :" at 3767.5,-1064.84 h60
  text ".plot_File_Name" at 5440.5,-1064.84 h60
  text "PLOT NAME =" at 6246,-1064.84 h60
M9 Title Sheet:
  drawing of 58 lines, arcs and shapes, not listed
  text "1" at 739.84,8036.5 h70
  text "2" at 3235.5,8036.5 h70
  text "3" at 5724.84,8036.5 h70
  text "4" at 8231.51,8036.5 h70
  text "5" at 10730.5,8036.5 h70
  text "6" at 13235.5,8036.5 h70
  text "A" at -416.5,6893.5 h70
  text "A" at 14383.5,6893.5 h70
  text "B" at -416.5,4513.5 h70
  text "B" at 14383.5,4513.5 h70
  text "C" at -416.5,2138.5 h70
  text "C" at 14383.5,2138.5 h70
  text "PROJECT TITLE:" at 11343.5,277.5 h45
  text ".PRJ_Title" at 11393.5,144.17 h70
  text "DESIGNED FOR:" at 11343.5,-23.5 h45
  text ".PRJ_Customer" at 11393.5,-163.5 h70
  text "D" at -416.5,-231.5 h70
  text "D" at 14383.5,-231.5 h70
  text "FILE NAME:" at 11343.5,-323.5 h45
  text ".PCB_File_Name_No_Path" at 11393.5,-443.5 h70
  text "Texas Instruments (TI) and/or its licensors do not warrant the accuracy or completeness of this specification" at 6374,-605.34 h45
  text "ENGINEER:" at 11343.5,-613.5 h45
  text "LAYOUT BY:" at 12848.5,-613.5 h45
  text "or any information contained therein. TI and/or its licensors do not warrant that this design will meet" at 6329.01,-718 h45
  text ".PRJ_Engineer" at 11393.5,-768.49 h70
  text ".PCB_Layout" at 12899,-768.49 h70
  text "the specifications, will be suitable for your application or fit for any particular purpose, or will operate in" at 6329.01,-830.67 h45
  text "ALTIUM DESIGNER VERSION:" at 12848.5,-923.5 h45
  text "an implementation. TI and/or its licensors do not warrant that the design is production worthy. You should" at 6329.01,-943.33 h45
  text "completely validate and test your design implementation to confirm the system functionality for your application." at 6374,-1056 h45
  text ".print_Scale" at 11393.5,-1056.83 h70
  text ".Application_BuildNumber" at 12899,-1056.83 h70
  text "1" at 739.84,-1263.5 h70
  text "2" at 3235.5,-1263.5 h70
  text "3" at 5724.84,-1263.5 h70
  text "4" at 8231.51,-1263.5 h70
  text "5" at 10730.5,-1263.5 h70
  text "6" at 13235.5,-1263.5 h70
M10 Fab Notes:
  drawing of 228 lines, arcs and shapes, not listed
  text "DESIGN INFORMATION" at 12385.02,6802 h60
  text "(REFER ALSO ARRAY/PANEL PROFILING INFORMATION)" at 12023.46,6640.29 h60
  text "BOARD SIZE" at 11337.46,6636 h60
  text "120 MM" at 11799.78,6508.18 h60
  text "X" at 12305.46,6508.18 h60
  text "82 MM" at 12536.78,6508.18 h60
  text "Number of Layers :" at 11740.46,6311 h60
  text "2" at 12835.27,6301 h60
  text "MIN. TRACK WIDTH:" at 11740.46,6172 h60
  text "10" at 12836.7,6172 h60
  text "MIL" at 12991.46,6172 h60
  text "MIN. CLEARANCE:" at 11740.46,6040 h60
  text "MIL" at 12991.46,6040 h60
  text "8" at 12828,6034 h60
  text "12" at 12819,5913 h60
  text "MIN. VIA DRILL SIZE:" at 11740.46,5908 h60
  text "MIL" at 12991.46,5908 h60
  text "MINIMUM ANNULAR RING" at 11411.23,5762 h60
  text "EXTERNAL" at 13432,5760 h60
  text "0.111mm (4.39 MIL)" at 12425,5759 h60
  text "PER" at 11611.23,5644 h60
  text "IPC-D-275 CLASS 2 LEVEL C" at 11831.23,5644 h60
  text "MIL, HOLES" at 13319.46,5531.71 h60
  text "+/-" at 12927,5531 h60
  text "+/-" at 13781,5531 h60
  text "REGISTRATION TOLERANCES:" at 11411.23,5526 h60
  text "METAL" at 12611,5526 h60
  text "5" at 13187.2,5526 h60
  text "3" at 14020.2,5526 h60
  text "MIL" at 14136.46,5526 h60
  text "MATERIAL:" at 11336.46,5316.54 h60
  text "FR-4 High Tg" at 12322.9,5176.21 h60
  text "FR-408" at 11757.46,5167.64 h60
  text "OTHER" at 13245.46,5167.64 h60
  text "X" at 12167,5160 h60
  text "63 MIL (1.6mm) +/-10%" at 12077.56,5004.92 h60
  text "THICKNESS:" at 11411.23,5000.64 h60
  text "X" at 11949.4,5000.64 h60
  text "OTHER" at 13362.46,5000.64 h60
  text "TOLERANCE:" at 11411.23,4842.64 h60
  text "X" at 12250.53,4842.64 h60
  text "ANSI IPC-6012 TYPE 3 CLASS 2" at 12437.48,4842.64 h60
  text "OTHER +/-" at 12437.46,4686.64 h60
  text "BOW & TWIST:" at 11411.23,4529.64 h60
  text "X" at 12250.53,4529.64 h60
  text "ANSI IPC-6012 TYPE 3 CLASS 2" at 12437.48,4529.64 h60
  text "OTHER +/-" at 12437.46,4371.13 h60
  text "COPPER THICKNESS (FINISHED):" at 11336.46,4235.64 h60
  text "X" at 13579,4084 h60
  text "1.4MIL (1oz)" at 12216.46,4082.92 h60
  text "2MIL (1.4oz)" at 12983.46,4082.92 h60
  text "2.8MIL (2oz)" at 13710.46,4082.92 h60
  text "OUTER:" at 11693.46,4078.64 h60
  text "1.4MIL (1oz)" at 12216.46,3925.92 h60
  text "2.8MIL (2oz)" at 12983.46,3925.92 h60
  text "N/A" at 13710,3926.29 h60
  text "INNER SIGNAL:" at 11404.38,3921.64 h60
  text "DRILLING:" at 11336.46,3782.64 h60
  text "REFERENCE:" at 11411.23,3665.64 h60
  text "X" at 12059.46,3665.64 h60
  text "AS SHOWN" at 12246.46,3665.64 h60
  text "X" at 12960.46,3665.64 h60
  text "NC_DRILL FILES" at 13097.46,3665.64 h60
  text "PTH MIN COPPER THICKNESS:" at 11411.23,3507.64 h60
  text "X" at 12761.46,3507.64 h60
  text "1MIL" at 12898.46,3507.64 h60
  text "OTHER" at 13395.46,3507.64 h60
  text "BOARD FINISH:" at 11336.46,3348.64 h60
  text "SILKSCREEN:" at 11491.68,3230.64 h60
  text "X" at 12440.46,3230.64 h60
  text "TOP" at 12566.46,3230.64 h60
  text "X" at 12950.46,3230.64 h60
  text "BOTTOM" at 13077.46,3230.64 h60
  text "SILKSCREEN COLOR:" at 11491.68,3063.64 h60
  text "X" at 12439.42,3063.64 h60
  text "WHITE" at 12566.46,3063.64 h60
  text "OTHER" at 13077.46,3063.64 h60
  text "SOLDER RESIST COLOR:" at 11491.68,2893.64 h60
  text "X" at 12059.42,2734.44 h60
  text "GREEN" at 12186.46,2734.44 h60
  text "BLUE" at 12777.46,2734.44 h60
  text "OTHER" at 13315.46,2734.44 h60
  text "IMMERSION GOLD (ENIG)" at 12397.46,2545.92 h60
  text "ENEPIG" at 13735,2542.64 h60
  text "SURFACE FINISH:" at 11336.46,2541.64 h60
  text "X" at 12210.51,2541.64 h60
  text "IMM. TIN/SILVER OR EQUIV" at 11666,2384.64 h60
  text "OTHER" at 13097.46,2384.64 h60
  text "ARRAY/PANEL:" at 11336.46,2205.64 h60
  text "CUT AND TRIM PER MECH LAYER 1" at 12397.46,2201.35 h60
  text "N.C. ROUTE" at 12397.46,2049.64 h60
  text "X" at 13076.46,2049.64 h60
  text "V. SCORE" at 13263.46,2049.64 h60
  text "CERTIFICATION:" at 11336.46,1912.64 h60
  text "MATERIALS AND WORKMANSHIP FOR ALL PCBS" at 12061.46,1912.64 h60
  text "TO MEET OR EXCEED THE REQUIREMENTS OF:" at 12061.46,1814.64 h60
  text "X" at 11687.96,1678.13 h60
  text "ANSI IPC-A-600F CLASS ->" at 11826.96,1678.13 h60
  text "X" at 13466.02,1678.13 h60
  text "2" at 13584.96,1678.14 h60
  text "1" at 13269.96,1676.64 h60
  text "3" at 13938.96,1676.64 h60
  text "X" at 11690.02,1518.64 h60
  text "UL 94V-0" at 11826.96,1518.64 h60
  text "X" at 12502.02,1518.64 h60
  text "RoHS" at 12638.96,1518.64 h60
  text "OTHER" at 13283.36,1518.64 h60
  text "PER ORDER" at 13680.42,1518.64 h60
  text "VIA TENTING:" at 12554,1385 h60
  text "ADDITIONAL REQUIREMENTS:" at 11336.46,1377.64 h60
  text "X" at 13636,1378 h60
  text "YES" at 13103.67,1375.92 h60
  text "NO" at 13468.47,1370.69 h60
  text "MICROSECTION:" at 11411.23,1262.64 h60
  text "YES" at 12316.96,1262.64 h60
  text "IMPEDANCE CONTROL:" at 12576,1256 h60
  text "YES" at 13560,1255 h60
  text "X" at 14102,1248 h60
  text "NO" at 13935.47,1237.69 h60
  text "REQUIRED" at 13178.46,1106.49 h60
  text "BARE BOARD ELEC. TEST:" at 11411.23,1103.64 h60
  text "NONE" at 12716.96,1103.64 h60
  text "X" at 13051.46,1103.64 h60
  text "PER ORDER" at 13770.46,1103.64 h60
  text "MANUFACTURER'S UL:" at 11411.23,946.64 h60
  text "RAIL" at 12576.96,942.35 h60
  text "METAL" at 13068.77,942.35 h60
  text "X" at 13444,942 h60
  text "SILK" at 13580.46,942.35 h60
M11 Gerber Information:
  lines w10: -292,-930.17 6308,-930.17 ; -292,-726.83 6310,-726.83 ; -292,-523.5 -292,-1133.5 3713,-1133.5 6310,-1133.5 6310,-523.5 -291.5,-523.5 -291.5,-1133.5 1284,-1133.5 ; 2173,-1133.5 2173,-523.5 ; 3440,-726.83 3440,-523.5 ; 4280,-726.83 4280,-523.5 ; 4902,-1140 4902,-937.17
  text "ALL ARTWORK VIEWED FROM TOP SIDE" at -228.5,-655.67 h60
  text "BOARD #:" at 2248,-655.67 h60
  text ".PRJ_Number" at 2793.5,-655.67 h60
  text "REV:" at 3638,-655.67 h60
  text ".PCB_Rev" at 3929.5,-655.67 h60
  text "SVN REV:" at 4476,-655.67 h60
  text ".VersionControl_RevNumber" at 4982,-655.67 h60
  text "LAYER NAME =" at -228.5,-858.49 h60
  text "PLOT NAME =" at -228.5,-1064.34 h60
  text ".plot_File_Name" at 577,-1064.34 h60
  text "GENERATED    :" at 2250,-1064.34 h60
  text ".Print_Date" at 3119.5,-1064.34 h60
  text ".Print_Time" at 3848.5,-1064.34 h60
  text "TEXAS INSTRUMENTS" at 5113,-1064.34 h60
M12 Stackup:
  lines w6: 11240,7617.33 14238,7617.33 ; 11240,7721.73 14238,7721.73 ; 11180,6935 ccw(c11214,6935) 11214,6901 14264,6901 ccw(c14264,6935) 14298,6935 14298,7937 ccw(c14264,7937) 14264,7971 11214,7971 ccw(c11214,7937) 11180,7937 11180,6935
  text "Layer Stack Up Detail for: TIDA-00701-RevB.PcbDoc" at 11240,7802.97 h58
  text "Layer" at 11240,7682.73 h24
  text "Gerber" at 11887.48,7682.73 h24
  text "Copper" at 12202.67,7682.73 h24
  text "Dielectric" at 12557.04,7682.73 h24
  text "Dielectric" at 12928.21,7682.73 h24
  text "Dielectric" at 13405.74,7682.73 h24
  text "Dielectric" at 13776.91,7682.73 h24
  text "Name" at 11240,7634.73 h24
  text "Document" at 11887.48,7634.73 h24
  text "Thickness" at 12202.67,7634.73 h24
  text "Height" at 12557.04,7634.73 h24
  text "Material" at 12928.21,7634.73 h24
  text "Constant" at 13405.74,7634.73 h24
  text "Type" at 13776.91,7634.73 h24
  text "Top Solder Mask" at 11240,7547.46 h34
  text "(.GTS)" at 11887.48,7547.46 h34
  text "0.4mil" at 12557.04,7547.46 h34
  text "Solder Resist" at 12928.21,7547.46 h34
  text "3.50" at 13405.74,7547.46 h34
  text "Top Layer" at 11240,7413.71 h34
  text "(.GTL)" at 11887.48,7413.71 h34
  text "2.8mil" at 12202.67,7413.71 h34
  text "59.2mil" at 12557.04,7346.83 h34
  text "FR-4 High Tg" at 12928.21,7346.83 h34
  text "4.80" at 13405.74,7346.83 h34
  text "Core" at 13776.91,7346.83 h34
  text "Bottom Layer" at 11240,7279.96 h34
  text "(.GBL)" at 11887.48,7279.96 h34
  text "2.8mil" at 12202.67,7279.96 h34
  text "Bottom Solder Mask" at 11240,7146.21 h34
  text "(.GBS)" at 11887.48,7146.21 h34
  text "0.4mil" at 12557.04,7146.21 h34
  text "Solder Resist" at 12928.21,7146.21 h34
  text "3.50" at 13405.74,7146.21 h34
M13 Component Bodies Top:
  text ".Layer_Name" at 577,-858.49 h60
M14 Component Bodies Bottom:
  text ".Layer_Name" at 577,-858.49 h60
M15 Courtyards Top:
  text ".Layer_Name" at 577,-858.49 h60
M16 Courtyards Bottom:
  text ".Layer_Name" at 577,-858.49 h60
Drill Drawing:
  text ".legend" at 26.5,3778.5 h60
  text "Drill Table" at 51.5,3593.5 h60
  text "FOR 12MIL DRILL +0/-12MIL" at 50,3482 h60
  text "FOR PTH DRILL +/-3MIL" at 50,3374 h60
  text "FOR NPTH DRILL +/-2MIL" at 45,3273 h60
  text ".Layer_Name" at 577,-858.49 h60

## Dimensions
0,0 to 0,3228.35 on M2 Board Dimensions
0,-410.5 to 1000,-410.5 on M2 Board Dimensions
0,0 to 4724.41,0 on M2 Board Dimensions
